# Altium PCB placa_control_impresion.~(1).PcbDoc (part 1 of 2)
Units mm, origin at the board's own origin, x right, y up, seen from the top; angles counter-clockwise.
Board outline 71.3 x 86.83 mm, 2 copper layers (Top Layer, Bottom Layer); 144 components, 32 nets, 580 pads, 404 vias.
Unrouted connection lines stored in the file: 1.
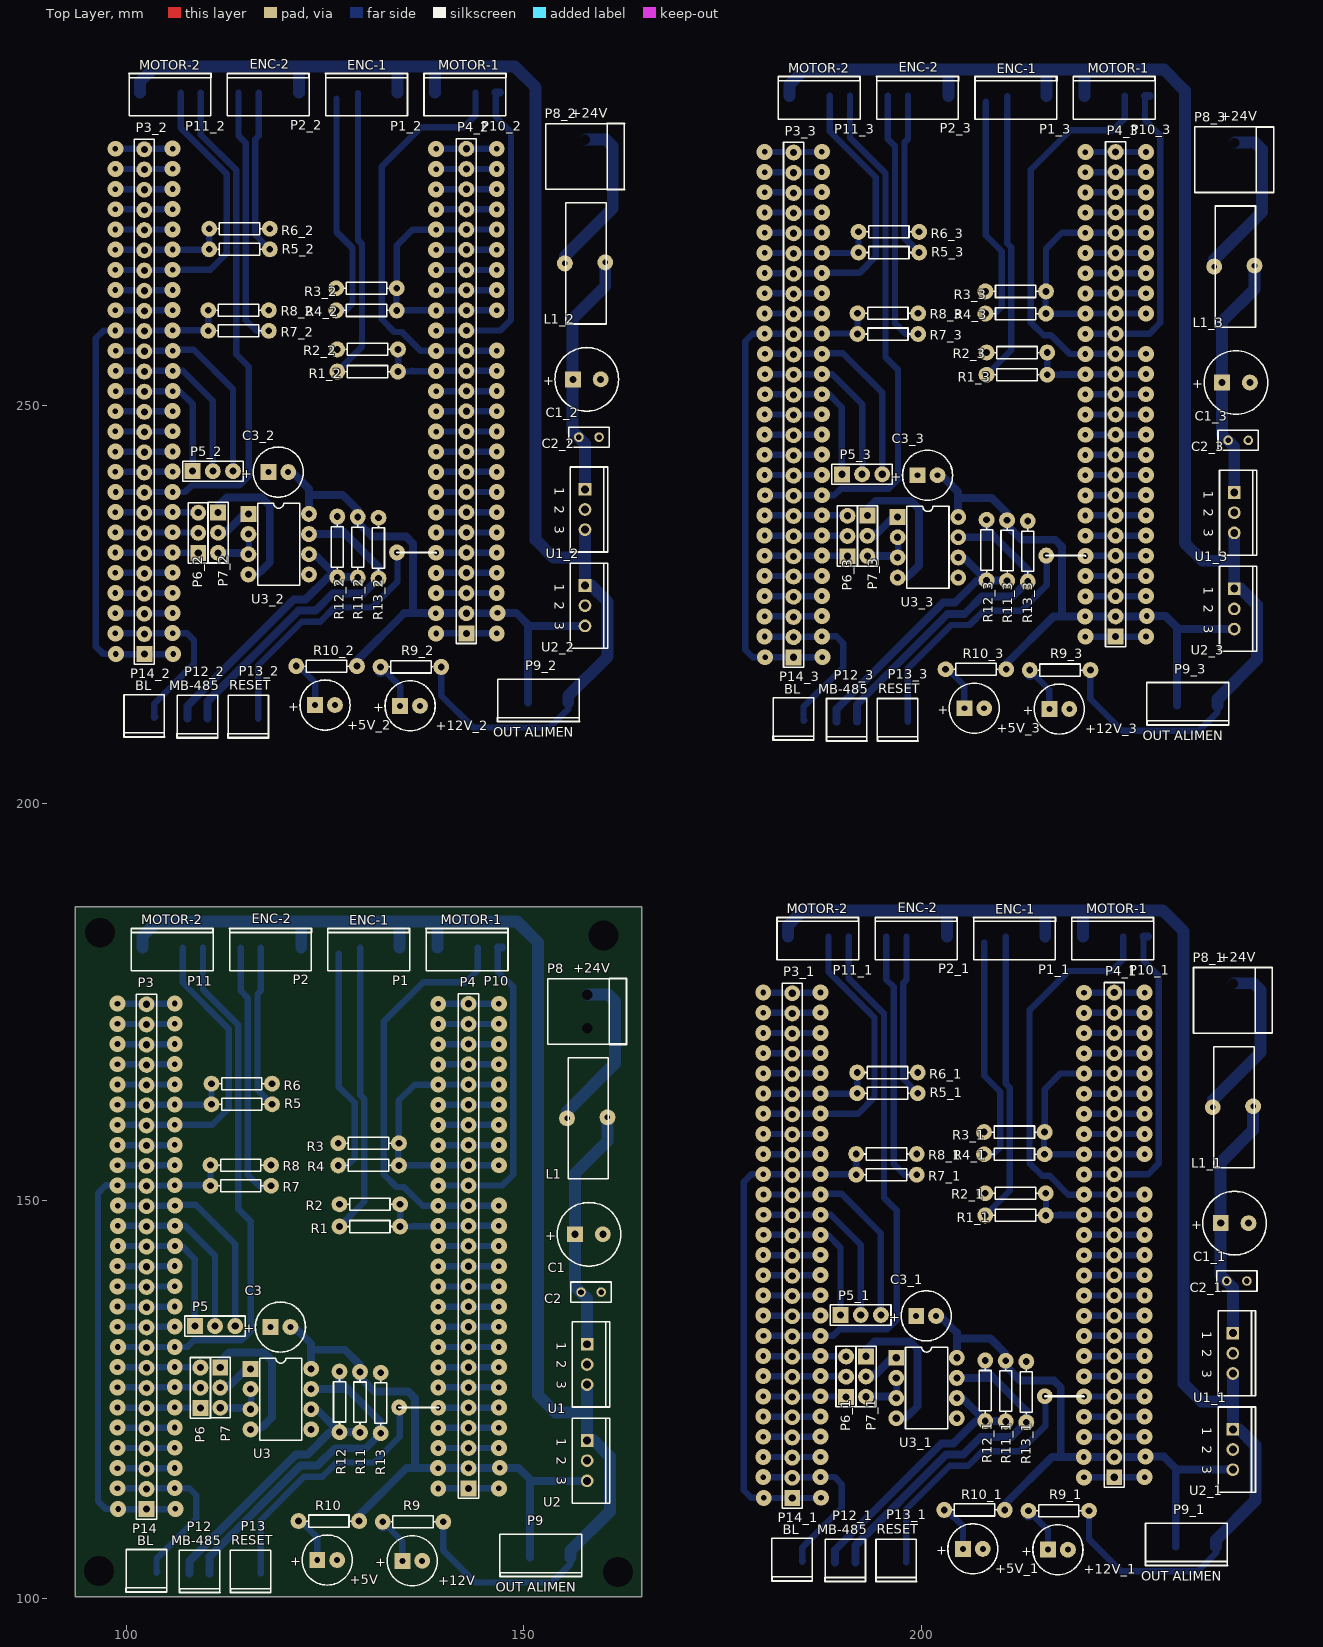
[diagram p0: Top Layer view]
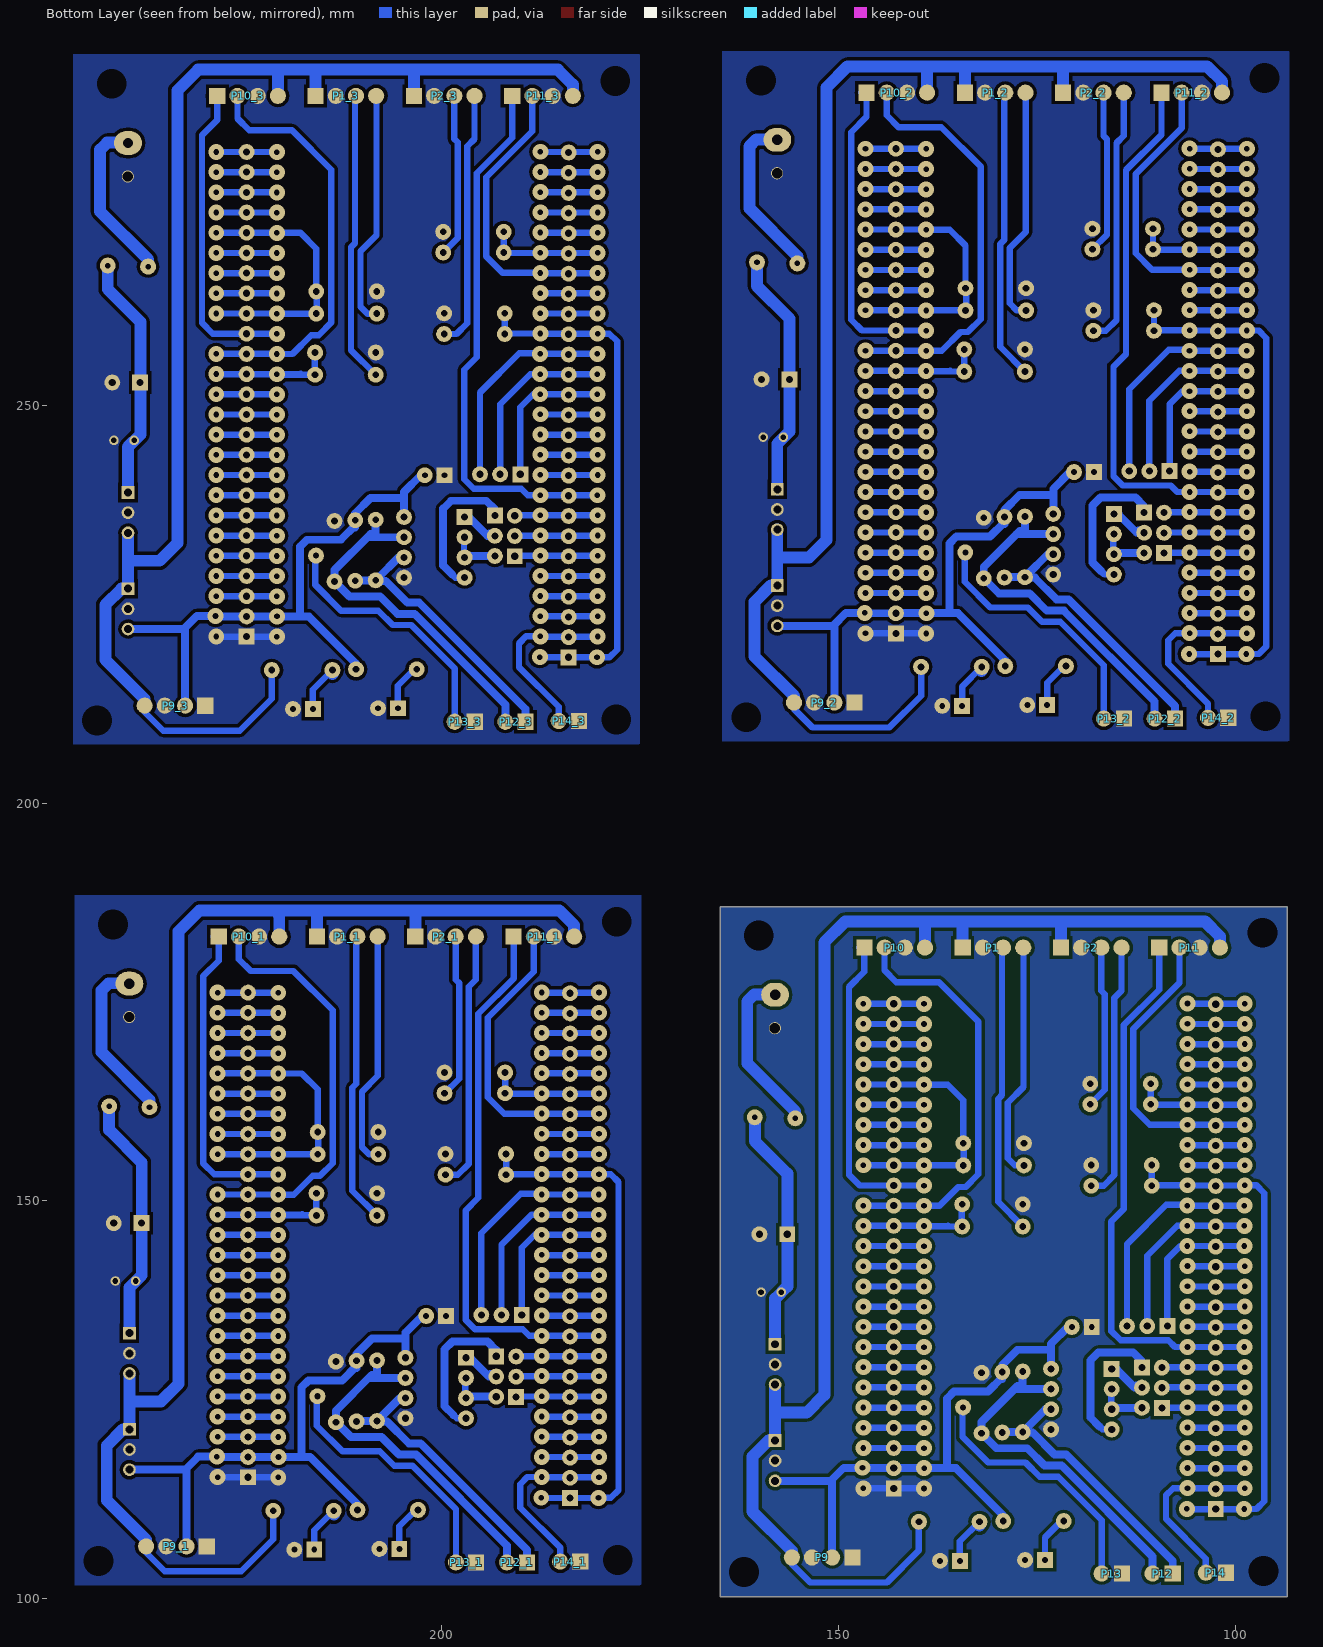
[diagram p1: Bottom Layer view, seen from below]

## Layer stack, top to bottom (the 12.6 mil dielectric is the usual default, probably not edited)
Top Layer: signal copper 0.0356
Dielectric: dielectric 0.32, FR-4, Dk 4.8
Bottom Layer: signal copper 0.0356

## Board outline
93.575,187.025 164.875,187.025 164.875,100.2 93.575,100.2

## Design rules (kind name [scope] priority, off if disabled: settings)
Clearance [All] p1: gap=0.4
ComponentClearance [All] p1: gap=0.254 collisioncheckmode=2 verticalgap=0.254
PlaneConnect [All] p1: planeconnectstyle=Direct reliefexpansion=0.508 reliefentries=4 reliefconductorwidth=0.6 reliefairgap=0.254
PolygonConnect [All] p1: connectstyle=Direct reliefconductorwidth=0.6 reliefentries=4 polygonreliefangle="90 Angle"
RoomDefinition REGULADOR_3 [InComponentClass('REGULADOR')] p1: confinementstyle=ConfineIn formatcopy=TRUE lockcomponents=FALSE outline 201.525,207.325 246.3,207.325 246.3,290.75 201.525,290.75
RoomDefinition INTERFAZ_3 [InComponentClass('INTERFAZ')] p2: confinementstyle=ConfineIn formatcopy=TRUE lockcomponents=FALSE outline 188.5,222.175 221.4,222.175 221.4,247.575 188.5,247.575
RoomDefinition ENCODER_3 [InComponentClass('ENCODER')] p3: confinementstyle=ConfineIn formatcopy=TRUE lockcomponents=FALSE outline 230.725,251.225 230.725,293.45 180.55,293.45 180.55,251.225
RoomDefinition BOARD-ARM_3 [InComponentClass('BOARD-ARM')] p4: confinementstyle=ConfineIn formatcopy=TRUE lockcomponents=FALSE outline 229.663,206.9 177.025,206.9 177.025,287.425 229.663,287.425
RoomDefinition placa_control_esquema_3 [InComponentClass('placa_control_esquema')] p5: confinementstyle=ConfineIn formatcopy=TRUE lockcomponents=FALSE outline 174.975,207.325 246.275,207.325 246.275,294.175 174.975,294.175
RoomDefinition REGULADOR_2 [InComponentClass('REGULADOR')] p6: confinementstyle=ConfineIn formatcopy=TRUE lockcomponents=FALSE outline 119.85,207.725 164.625,207.725 164.625,291.15 119.85,291.15
RoomDefinition INTERFAZ_2 [InComponentClass('INTERFAZ')] p7: confinementstyle=ConfineIn formatcopy=TRUE lockcomponents=FALSE outline 106.825,222.575 139.725,222.575 139.725,247.975 106.825,247.975
RoomDefinition ENCODER_2 [InComponentClass('ENCODER')] p8: confinementstyle=ConfineIn formatcopy=TRUE lockcomponents=FALSE outline 149.05,251.625 149.05,293.85 98.875,293.85 98.875,251.625
RoomDefinition BOARD-ARM_2 [InComponentClass('BOARD-ARM')] p9: confinementstyle=ConfineIn formatcopy=TRUE lockcomponents=FALSE outline 147.988,207.3 95.35,207.3 95.35,287.825 147.988,287.825
RoomDefinition placa_control_esquema_2 [InComponentClass('placa_control_esquema')] p10: confinementstyle=ConfineIn formatcopy=TRUE lockcomponents=FALSE outline 93.3,207.725 164.6,207.725 164.6,294.575 93.3,294.575
RoomDefinition REGULADOR_1 [InComponentClass('REGULADOR')] p11: confinementstyle=ConfineIn formatcopy=TRUE lockcomponents=FALSE outline 201.35,101.575 246.125,101.575 246.125,185 201.35,185
RoomDefinition INTERFAZ_1 [InComponentClass('INTERFAZ')] p12: confinementstyle=ConfineIn formatcopy=TRUE lockcomponents=FALSE outline 188.325,116.425 221.225,116.425 221.225,141.825 188.325,141.825
RoomDefinition ENCODER_1 [InComponentClass('ENCODER')] p13: confinementstyle=ConfineIn formatcopy=TRUE lockcomponents=FALSE outline 230.55,145.475 230.55,187.7 180.375,187.7 180.375,145.475
RoomDefinition BOARD-ARM_1 [InComponentClass('BOARD-ARM')] p14: confinementstyle=ConfineIn formatcopy=TRUE lockcomponents=FALSE outline 229.488,101.15 176.85,101.15 176.85,181.675 229.488,181.675
RoomDefinition placa_control_esquema_1 [InComponentClass('placa_control_esquema')] p15: confinementstyle=ConfineIn formatcopy=TRUE lockcomponents=FALSE outline 174.8,101.575 246.1,101.575 246.1,188.425 174.8,188.425
RoomDefinition REGULADOR [InComponentClass('REGULADOR')] p16: confinementstyle=ConfineIn formatcopy=TRUE lockcomponents=FALSE outline 120.125,100.175 164.9,100.175 164.9,183.6 120.125,183.6
RoomDefinition INTERFAZ [InComponentClass('INTERFAZ')] p17: confinementstyle=ConfineIn formatcopy=TRUE lockcomponents=FALSE outline 107.1,115.025 140,115.025 140,140.425 107.1,140.425
RoomDefinition ENCODER [InComponentClass('ENCODER')] p18: confinementstyle=ConfineIn formatcopy=TRUE lockcomponents=FALSE outline 149.325,144.075 149.325,186.3 99.15,186.3 99.15,144.075
RoomDefinition BOARD-ARM [InComponentClass('BOARD-ARM')] p19: confinementstyle=ConfineIn formatcopy=TRUE lockcomponents=FALSE outline 148.263,99.75 95.625,99.75 95.625,180.275 148.263,180.275
RoomDefinition placa_control_esquema [InComponentClass('placa_control_esquema')] p20: confinementstyle=ConfineIn formatcopy=TRUE lockcomponents=FALSE outline 93.575,100.175 164.875,100.175 164.875,187.025 93.575,187.025
RoutingVias [All] p1: holewidth=0.711 width=2 viastyle="Through Hole" minholewidth=0.711 minwidth=1.27 maxholewidth=0.711 maxwidth=2
SolderMaskExpansion [All] p1: expansion=0.102
TestPointUsage [All] p1: valid=0 allowmultiple=FALSE
Testpoint [All] p1: side=15 testpointundercomponent=TRUE minsize=1.016 maxsize=2.54 preferedsize=1.524 minholesize=0 maxholesize=1.016 preferedholesize=0.813 testpointgrid=0.025 style=1023 order=0-112345678
Width [All] p1: maxlimit=1.5 minlimit=0.8 preferedwidth=0.8
17 further rules are at their usual default settings.

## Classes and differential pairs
component class INTERFAZ: C3 P12 R11 R12 R13 U3
component class ENCODER: P1 P2 R1 R2 R3 R4 R5 R6 R7 R8
component class BOARD-ARM: P3 P4 P5 P6 P7 P13 P14
component class REGULADOR: +5V +12V C1 C2 L1 P8 R9 R10 U1 U2
component class placa_control_esquema: P9 P10 P11

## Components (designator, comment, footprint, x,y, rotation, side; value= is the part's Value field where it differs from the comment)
+5V "LED2" CAPPR2.5-6.3X5 125.275,104.825 r0 top
+5V_1 "LED2" CAPPR2.5-6.3X5 206.5,106.225 r0 top (schematic designator +5V)
+5V_2 "LED2" CAPPR2.5-6.3X5 125,212.375 r0 top (schematic designator +5V)
+5V_3 "LED2" CAPPR2.5-6.3X5 206.675,211.975 r0 top (schematic designator +5V)
+12V "LED2" CAPPR2.5-6.3X5 135.975,104.725 r0 top
+12V_1 "LED2" CAPPR2.5-6.3X5 217.2,106.125 r0 top (schematic designator +12V)
+12V_2 "LED2" CAPPR2.5-6.3X5 135.7,212.275 r0 top (schematic designator +12V)
+12V_3 "LED2" CAPPR2.5-6.3X5 217.375,211.875 r0 top (schematic designator +12V)
C1 "Cap Pol3" CAPPR3.5-8X15 158.2,145.8 r0 top
C1_1 "Cap Pol3" CAPPR3.5-8X15 239.425,147.2 r0 top (schematic designator C1)
C1_2 "Cap Pol3" CAPPR3.5-8X15 157.925,253.35 r0 top (schematic designator C1)
C1_3 "Cap Pol3" CAPPR3.5-8X15 239.6,252.95 r0 top (schematic designator C1)
C2 "Cap" RAD-0.1 158.475,138.525 r180 top
C2_1 "Cap" RAD-0.1 239.7,139.925 r180 top (schematic designator C2)
C2_2 "Cap" RAD-0.1 158.2,246.075 r180 top (schematic designator C2)
C2_3 "Cap" RAD-0.1 239.875,245.675 r180 top (schematic designator C2)
C3 "Cap" CAPPR2.5-6.3X5 119.394,134.133 r0 top
C3_1 "Cap" CAPPR2.5-6.3X5 200.619,135.533 r0 top (schematic designator C3)
C3_2 "Cap" CAPPR2.5-6.3X5 119.119,241.683 r0 top (schematic designator C3)
C3_3 "Cap" CAPPR2.5-6.3X5 200.794,241.283 r0 top (schematic designator C3)
L1 "Inductor Iron" bobina_Choque 155.575,162.925 r270 top
L1_1 "Inductor Iron" bobina_Choque 236.8,164.325 r270 top (schematic designator L1)
L1_2 "Inductor Iron" bobina_Choque 155.3,270.475 r270 top (schematic designator L1)
L1_3 "Inductor Iron" bobina_Choque 236.975,270.075 r270 top (schematic designator L1)
P1 "ENC-1" HDR1X5 126.758,189.475 r180 top
P1_1 "ENC-1" HDR1X5 207.983,190.875 r180 top (schematic designator P1)
P1_2 "ENC-1" HDR1X5 126.483,297.025 r180 top (schematic designator P1)
P1_3 "ENC-1" HDR1X5 208.158,296.625 r180 top (schematic designator P1)
P2 "ENC-2" HDR1X5 114.392,189.475 r180 top
P2_1 "ENC-2" HDR1X5 195.617,190.875 r180 top (schematic designator P2)
P2_2 "ENC-2" HDR1X5 114.117,297.025 r180 top (schematic designator P2)
P2_3 "ENC-2" HDR1X5 195.792,296.625 r180 top (schematic designator P2)
P3 "header26" HDR1x26 107.625,144.25 r90 top
P3_1 "header26" HDR1x26 188.85,145.65 r90 top (schematic designator P3)
P3_2 "header26" HDR1x26 107.35,251.8 r90 top (schematic designator P3)
P3_3 "header26" HDR1x26 189.025,251.4 r90 top (schematic designator P3)
P4 "Header 25" HDR1X25 143.055,113.84 r90 top
P4_1 "Header 25" HDR1X25 224.28,115.24 r90 top (schematic designator P4)
P4_2 "Header 25" HDR1X25 142.78,221.39 r90 top (schematic designator P4)
P4_3 "Header 25" HDR1X25 224.455,220.99 r90 top (schematic designator P4)
P5 "Header 3" HDR1X3 108.625,134.25 r0 top
P5_1 "Header 3" HDR1X3 189.85,135.65 r0 top (schematic designator P5)
P5_2 "Header 3" HDR1X3 108.35,241.8 r0 top (schematic designator P5)
P5_3 "Header 3" HDR1X3 190.025,241.4 r0 top (schematic designator P5)
P6 "Header 3" HDR1X3 109.325,123.95 r90 top
P6_1 "Header 3" HDR1X3 190.55,125.35 r90 top (schematic designator P6)
P6_2 "Header 3" HDR1X3 109.05,231.5 r90 top (schematic designator P6)
P6_3 "Header 3" HDR1X3 190.725,231.1 r90 top (schematic designator P6)
P7 "Header 3" HDR1X3 111.825,129.05 r270 top
P7_1 "Header 3" HDR1X3 193.05,130.45 r270 top (schematic designator P7)
P7_2 "Header 3" HDR1X3 111.55,236.6 r270 top (schematic designator P7)
P7_3 "Header 3" HDR1X3 193.225,236.2 r270 top (schematic designator P7)
P8 "+24V" PWHEADER1X2 157.975,174.025 r90 top
P8_1 "+24V" PWHEADER1X2 239.2,175.425 r90 top (schematic designator P8)
P8_2 "+24V" PWHEADER1X2 157.7,281.575 r90 top (schematic designator P8)
P8_3 "+24V" PWHEADER1X2 239.375,281.175 r90 top (schematic designator P8)
P9 "OUT ALIMEN" HDR1X5 155.875,97.525 r0 top
P9_1 "OUT ALIMEN" HDR1X5 237.1,98.925 r0 top (schematic designator P9)
P9_2 "OUT ALIMEN" HDR1X5 155.6,205.075 r0 top (schematic designator P9)
P9_3 "OUT ALIMEN" HDR1X5 237.275,204.675 r0 top (schematic designator P9)
P10 "MOTOR-1" HDR1X5 139.125,189.475 r180 top
P10_1 "MOTOR-1" HDR1X5 220.35,190.875 r180 top (schematic designator P10)
P10_2 "MOTOR-1" HDR1X5 138.85,297.025 r180 top (schematic designator P10)
P10_3 "MOTOR-1" HDR1X5 220.525,296.625 r180 top (schematic designator P10)
P11 "MOTOR-2" HDR1X5 102.025,189.475 r180 top
P11_1 "MOTOR-2" HDR1X5 183.25,190.875 r180 top (schematic designator P11)
P11_2 "MOTOR-2" HDR1X5 101.75,297.025 r180 top (schematic designator P11)
P11_3 "MOTOR-2" HDR1X5 183.425,296.625 r180 top (schematic designator P11)
P12 "MB-485" wf2s 115.575,103.125 r0 top
P12_1 "MB-485" wf2s 196.8,104.525 r0 top (schematic designator P12)
P12_2 "MB-485" wf2s 115.3,210.675 r0 top (schematic designator P12)
P12_3 "MB-485" wf2s 196.975,210.275 r0 top (schematic designator P12)
P13 "RESET" wf2s 121.975,103.125 r0 top
P13_1 "RESET" wf2s 203.2,104.525 r0 top (schematic designator P13)
P13_2 "RESET" wf2s 121.7,210.675 r0 top (schematic designator P13)
P13_3 "RESET" wf2s 203.375,210.275 r0 top (schematic designator P13)
P14 "BL" wf2s 108.875,103.225 r0 top
P14_1 "BL" wf2s 190.1,104.625 r0 top (schematic designator P14)
P14_2 "BL" wf2s 108.6,210.775 r0 top (schematic designator P14)
P14_3 "BL" wf2s 190.275,210.375 r0 top (schematic designator P14)
R1 "metal film 2%" AXIAL-0.3 130.634,146.777 r180 top
R1_1 "metal film 2%" AXIAL-0.3 211.859,148.177 r180 top (schematic designator R1)
R1_2 "metal film 2%" AXIAL-0.3 130.359,254.327 r180 top (schematic designator R1)
R1_3 "metal film 2%" AXIAL-0.3 212.034,253.927 r180 top (schematic designator R1)
R2 "metal film 2%" AXIAL-0.3 130.634,149.569 r0 top
R2_1 "metal film 2%" AXIAL-0.3 211.859,150.969 r0 top (schematic designator R2)
R2_2 "metal film 2%" AXIAL-0.3 130.359,257.119 r0 top (schematic designator R2)
R2_3 "metal film 2%" AXIAL-0.3 212.034,256.719 r0 top (schematic designator R2)
R3 "metal film 2%" AXIAL-0.3 130.484,154.468 r180 top
R3_1 "metal film 2%" AXIAL-0.3 211.709,155.868 r180 top (schematic designator R3)
R3_2 "metal film 2%" AXIAL-0.3 130.209,262.018 r180 top (schematic designator R3)
R3_3 "metal film 2%" AXIAL-0.3 211.884,261.618 r180 top (schematic designator R3)
R4 "metal film 2%" AXIAL-0.3 130.484,157.26 r0 top
R4_1 "metal film 2%" AXIAL-0.3 211.709,158.66 r0 top (schematic designator R4)
R4_2 "metal film 2%" AXIAL-0.3 130.209,264.81 r0 top (schematic designator R4)
R4_3 "metal film 2%" AXIAL-0.3 211.884,264.41 r0 top (schematic designator R4)
R5 "metal film 2%" AXIAL-0.3 114.525,162.15 r0 top
R5_1 "metal film 2%" AXIAL-0.3 195.75,163.55 r0 top (schematic designator R5)
R5_2 "metal film 2%" AXIAL-0.3 114.25,269.7 r0 top (schematic designator R5)
R5_3 "metal film 2%" AXIAL-0.3 195.925,269.3 r0 top (schematic designator R5)
R6 "metal film 2%" AXIAL-0.3 114.525,164.75 r180 top
R6_1 "metal film 2%" AXIAL-0.3 195.75,166.15 r180 top (schematic designator R6)
R6_2 "metal film 2%" AXIAL-0.3 114.25,272.3 r180 top (schematic designator R6)
R6_3 "metal film 2%" AXIAL-0.3 195.925,271.9 r180 top (schematic designator R6)
R7 "metal film 2%" AXIAL-0.3 114.4,151.9 r0 top
R7_1 "metal film 2%" AXIAL-0.3 195.625,153.3 r0 top (schematic designator R7)
R7_2 "metal film 2%" AXIAL-0.3 114.125,259.45 r0 top (schematic designator R7)
R7_3 "metal film 2%" AXIAL-0.3 195.8,259.05 r0 top (schematic designator R7)
R8 "metal film 2%" AXIAL-0.3 114.4,154.5 r180 top
R8_1 "metal film 2%" AXIAL-0.3 195.625,155.9 r180 top (schematic designator R8)
R8_2 "metal film 2%" AXIAL-0.3 114.125,262.05 r180 top (schematic designator R8)
R8_3 "metal film 2%" AXIAL-0.3 195.8,261.65 r180 top (schematic designator R8)
R9 "Carbon 1/8w 5%" AXIAL-0.3 136.075,109.625 r0 top
R9_1 "Carbon 1/8w 5%" AXIAL-0.3 217.3,111.025 r0 top (schematic designator R9)
R9_2 "Carbon 1/8w 5%" AXIAL-0.3 135.8,217.175 r0 top (schematic designator R9)
R9_3 "Carbon 1/8w 5%" AXIAL-0.3 217.475,216.775 r0 top (schematic designator R9)
R10 "Carbon 1/8w 5%" AXIAL-0.3 125.475,109.725 r0 top
R10_1 "Carbon 1/8w 5%" AXIAL-0.3 206.7,111.125 r0 top (schematic designator R10)
R10_2 "Carbon 1/8w 5%" AXIAL-0.3 125.2,217.275 r0 top (schematic designator R10)
R10_3 "Carbon 1/8w 5%" AXIAL-0.3 206.875,216.875 r0 top (schematic designator R10)
R11 "Carbon 1/8w 5%" AXIAL-0.3 129.4,124.675 r90 top
R11_1 "Carbon 1/8w 5%" AXIAL-0.3 210.625,126.075 r90 top (schematic designator R11)
R11_2 "Carbon 1/8w 5%" AXIAL-0.3 129.125,232.225 r90 top (schematic designator R11)
R11_3 "Carbon 1/8w 5%" AXIAL-0.3 210.8,231.825 r90 top (schematic designator R11)
R12 "Carbon 1/8w 5%" AXIAL-0.3 126.826,124.725 r270 top
R12_1 "Carbon 1/8w 5%" AXIAL-0.3 208.051,126.125 r270 top (schematic designator R12)
R12_2 "Carbon 1/8w 5%" AXIAL-0.3 126.551,232.275 r270 top (schematic designator R12)
R12_3 "Carbon 1/8w 5%" AXIAL-0.3 208.226,231.875 r270 top (schematic designator R12)
R13 "Carbon 1/8w 5%" AXIAL-0.3 132,124.575 r270 top
R13_1 "Carbon 1/8w 5%" AXIAL-0.3 213.225,125.975 r270 top (schematic designator R13)
R13_2 "Carbon 1/8w 5%" AXIAL-0.3 131.725,232.125 r270 top (schematic designator R13)
R13_3 "Carbon 1/8w 5%" AXIAL-0.3 213.4,231.725 r270 top (schematic designator R13)
U1 "LM78L12ACZ" T03B 157.975,129.425 r270 top
U1_1 "LM78L12ACZ" T03B 239.2,130.825 r270 top (schematic designator U1)
U1_2 "LM78L12ACZ" T03B 157.7,236.975 r270 top (schematic designator U1)
U1_3 "LM78L12ACZ" T03B 239.375,236.575 r270 top (schematic designator U1)
U2 "LM78L05ACZ" T03B 157.975,117.325 r270 top
U2_1 "LM78L05ACZ" T03B 239.2,118.725 r270 top (schematic designator U2)
U2_2 "LM78L05ACZ" T03B 157.7,224.875 r270 top (schematic designator U2)
U2_3 "LM78L05ACZ" T03B 239.375,224.475 r270 top (schematic designator U2)
U3 "SN75176BP" 626-05 119.444,125.065 r270 top
U3_1 "SN75176BP" 626-05 200.669,126.465 r270 top (schematic designator U3)
U3_2 "SN75176BP" 626-05 119.169,232.615 r270 top (schematic designator U3)
U3_3 "SN75176BP" 626-05 200.844,232.215 r270 top (schematic designator U3)

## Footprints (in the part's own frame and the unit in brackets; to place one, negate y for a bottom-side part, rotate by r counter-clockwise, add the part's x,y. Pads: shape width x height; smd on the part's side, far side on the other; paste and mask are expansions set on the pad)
626-05 [mm] "DIP; 8 Leads; Row Spacing 7.62 mm; Pitch 2.54 mm"
  rect 2x2 hole 0.9: 1(-3.81,-3.81)
  round 2 hole 0.9: 2(-1.27,-3.81) 3(1.27,-3.81) 4(3.81,-3.81) 5(3.81,3.81) 6(1.27,3.81) 7(-1.27,3.81) 8(-3.81,3.81)
  silkscreen extent -5.15,-2.65 5.15,2.65
AXIAL-0.3 [mm] "Resistor; 2 Leads"
  round 2 hole 0.85: 1(-3.81,0) 2(3.81,0)
  silkscreen extent -2.77,-0.76 2.77,0.76
bobina_Choque [mm]
  round 2 hole 0.7: 1(2.54,-0.127) 2(2.413,4.953)
  silkscreen extent -5.08,0 10.16,5.08
CAPPR2.5-6.3X5 [mm] "Capacitor, Electrolytic, Radial; Body 6.3 x 5 mm (Dia.xH typ); Pin Spacing 2.5 mm (typ)"
  rect 2x2 hole 0.75: 1(-1.25,0)
  round 2 hole 0.75: 2(1.25,0)
  silkscreen extent -3.15,-3.15 3.15,3.15
CAPPR3.5-8X15 [mm] "Capacitor, Electrolytic, Radial; Body 8 x 15 mm (Dia.xH typ); Pin Spacing 3.5 mm (typ)"
  rect 2x2 hole 0.9: 1(-1.75,0)
  round 2 hole 0.9: 2(1.75,0)
  silkscreen extent -4,-4 4,4
HDR1X3 [mm] "Connector; Header; 3 Position"
  rect 2x2 hole 0.9: 1(0,0)
  round 2 hole 0.9: 2(2.54,0) 3(5.08,0)
  silkscreen extent -1.27,-1.27 6.35,1.27
HDR1X5 [mil]
  rect 80x80 smd far side: 1(-300,300)
  round 80 smd far side: 2(-200,300) 3(-100,300) 4(0,300)
  silkscreen extent -350,205 55,415
HDR1X25 [mm] "Connector; Header; 25 Position"
  rect 2x2 hole 0.9: 1(0,0)
  round 2 hole 0.9: 2(2.54,0) 3(5.08,0) 4(7.62,0) 5(10.16,0) 6(12.7,0) 7(15.24,0) 8(17.78,0) 9(20.32,0) 10(22.86,0) 11(25.4,0) 12(27.94,0) 13(30.48,0) 14(33.02,0) 15(35.56,0) 16(38.1,0) 17(40.64,0) 18(43.18,0) 19(45.72,0) 20(48.26,0) 21(50.8,0) 22(53.34,0) 23(55.88,0) 24(58.42,0) 25(60.96,0)
  silkscreen extent -1.27,-1.27 62.23,1.27
HDR1x26 [mm]
  rect 2x2 hole 0.9: 1(-33.02,5.08)
  round 2 hole 0.9: 2(-30.48,5.08) 3(-27.94,5.08) 4(-25.4,5.08) 5(-22.86,5.08) 6(-20.32,5.08) 7(-17.78,5.08) 8(-15.24,5.08) 9(-12.7,5.08) 10(-10.16,5.08) 11(-7.62,5.08) 12(-5.08,5.08) 13(-2.54,5.08) 14(0,5.08) 15(2.54,5.08) 16(5.08,5.08) 17(7.62,5.08) 18(10.16,5.08) 19(12.7,5.08) 20(15.24,5.08) 21(17.78,5.08) 22(20.32,5.08) 23(22.86,5.08) 24(25.4,5.08) 25(27.94,5.08) 26(30.48,5.08)
  silkscreen extent -34.29,3.81 31.75,6.35
PWHEADER1X2 [mm]
  round 0 / inner round 0 / far side oval 3x3.5 hole 1.3: 2(1.905,0)
  silkscreen extent -4.32,-4.95 3.94,4.95
RAD-0.1 [mm] "Indicating Instrument; 2 Leads"
  round 1.2 hole 0.7: 1(-1.27,0) 2(1.27,0)
  silkscreen extent -2.54,-1.27 2.54,1.27
T03B [mm] "TO, Thru-Hole, Vertical, Heatsink Mounted; 3 In-Line Leads; Pitch 2.54 mm"
  rect 1.6x1.6 hole 1: 1(-2.54,0)
  round 1.6 hole 1: 2(0,0) 3(2.54,0)
  silkscreen extent -5.35,-1.85 5.35,2.85
wf2s [mil]
  rect 80x80 smd far side: 1(-300,0)
  round 80 smd far side: 2(-200,0)
  silkscreen extent -350,-95 -150,115

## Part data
+5V +5V_1 +5V_2 +5V_3 +12V +12V_1 +12V_2 +12V_3: "Typical RED, GREEN, YELLOW, AMBER GaAs LED"
C1 C1_1 C1_2 C1_3: "Polarized Capacitor 35V"
C2 C2_1 C2_2 C2_3 C3 C3_1 C3_2 C3_3: "Capacitor"
L1 L1_1 L1_2 L1_3: "Magnetic-Core Inductor"
P1 P1_1 P1_2 P1_3 P2 P2_1 P2_2 P2_3 P9 P9_1 P9_2 P9_3 P10 P10_1 P10_2 P10_3 P11 P11_1 P11_2 P11_3: library part "Header 4", "Header, 4-Pin"
P3 P3_1 P3_2 P3_3: library part Component_1
P4 P4_1 P4_2 P4_3: "Header, 25-Pin"
P5 P5_1 P5_2 P5_3 P6 P6_1 P6_2 P6_3 P7 P7_1 P7_2 P7_3: "Header, 3-Pin"
P8 P8_1 P8_2 P8_3 P12 P12_1 P12_2 P12_3 P13 P13_1 P13_2 P13_3 P14 P14_1 P14_2 P14_3: library part "Header 2", "Header, 2-Pin"
R1 R1_1 R1_2 R1_3 R2 R2_1 R2_2 R2_3 R3 R3_1 R3_2 R3_3 R4 R4_1 R4_2 R4_3 R5 R5_1 R5_2 R5_3 R6 R6_1 R6_2 R6_3 R7 R7_1 R7_2 R7_3 R8 R8_1 R8_2 R8_3 R9 R9_1 R9_2 R9_3 R10 R10_1 R10_2 R10_3 R11 R11_1 R11_2 R11_3 R12 R12_1 R12_2 R12_3 R13 R13_1 R13_2 R13_3: library part "Res Semi", "Semiconductor Resistor"
U1 U1_1 U1_2 U1_3 U2 U2_1 U2_2 U2_3: "3-Terminal Positive Regulator"
U3 U3_1 U3_2 U3_3: "Differential Bus Transceiver"

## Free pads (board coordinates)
  round 1.524 hole 3.75: 0(96.275,210.975) 0(96.4,291.275) 0(96.55,103.425) 0(96.675,183.725) 0(159.75,290.925) 0(160.025,183.375) 0(161.6,210.85) 0(161.875,103.3) 0(177.775,104.825) 0(177.9,185.125) 0(177.95,210.575) 0(178.075,290.875) 0(241.25,184.775) 0(241.425,290.525) 0(243.1,104.7) 0(243.275,210.45)
  round 2 hole 0.762: 0(134.05,231.575) 0(134.325,124.025) 0(215.55,125.425) 0(215.725,231.175)
  round 0 / inner round 0 / far side round 1.524 hole 1.3: 0(157.725,279.275) 0(158,171.725) 0(239.225,173.125) 0(239.4,278.875)

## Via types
v1: diameter 2, hole 0.711, Top Layer to Bottom Layer, 404 vias

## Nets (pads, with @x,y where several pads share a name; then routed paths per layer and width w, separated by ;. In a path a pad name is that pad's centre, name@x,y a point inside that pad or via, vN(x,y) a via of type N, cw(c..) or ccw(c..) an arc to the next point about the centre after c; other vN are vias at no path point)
+5V: C3.2 P4.2 P9.2 R10.2 R11.2 U2.3 U3.8 | length 71.6
  Bottom Layer w1: C3.2@121.142,134.133 123.254,132.021 U3.8@123.254,128.875 U3.8@123.475,128.875 ; 123.254,131.275 127.475,131.275 R11.2@129.4,129.35 ; R10.2@129.285,109.725 129.285,110.435 135.23,116.38 P4.2@143.055,116.38 143.06,116.375 v1@146.325,116.375 ; R11.2@129.4,127.575 129.4,127.825 131.207,126.018 135.457,126.018 136.325,125.15 136.325,116.475 ; v1(146.975,116.425) 149.325,116.425 150.965,114.785 U2.3@157.975,114.785 ; P9.2@150.795,105.145 150.795,114.605
  other v1: 139.225,116.38
+12V: P1.1 P2.1 P9.4 P10.4 P11.4 R9.2 U1.3 U2.1 | length 173.9
  Bottom Layer w0.8: R9.2@139.885,109.625 139.885,106.015 143.9,102 153.55,102 155.875,104.325 P9.4@155.875,105.145
  Bottom Layer w1.5: P11.4@102.025,181.855 102.025,183.275 103.9,185.15 149.15,185.15 151.775,182.525 151.775,125.6 154,123.375 157.975,123.375 ; P2.1@122.012,181.855 122.012,184.637 122.025,184.65 ; P1.1@134.378,181.855 134.378,184.603 134.425,184.65 ; P10.4@139.125,181.855 139.125,184.575 139.2,184.65 ; P9.4@155.875,105.145 155.875,105.975 160.825,110.925 160.825,114.15 ; U1.3@157.975,126.885 U2.1@157.975,119.865 158.785,119.865 160.825,117.825 160.825,114.275
D/~E: P7.3 U3.2 U3.3 | length 6.7
  Bottom Layer w0.8: U3.3@115.634,123.795 115.71,123.87 115.71,126.365 U3.2@115.75,126.325
  Bottom Layer w1: P7.3@111.825,123.97 115.459,123.97 U3.3@115.634,123.795 ; U3.3@115.615,124.27 U3.3@115.71,124.175
D/~E_0: P3.14 P5.1 | length 18.8
  Bottom Layer w0.8: v1(98.94,144.32) 107.005,144.32 108.625,142.7 P5.1@108.625,134.25
  other v1: 106.125,144.32
D/~E_1: P3.6 P6.1 | length 10.4
  Bottom Layer w0.8: v1@98.94,124 109.275,124 P6.1@109.325,123.95
  other v1: 98.9,124.01 106.1,124.025
DRIVER: P7.1 U3.4 | length 18.6
  Bottom Layer w0.8: U3.4@115.634,121.255 116.805,121.255 117.187,121.637
  Bottom Layer w1: P7.1@111.825,129.05 111.825,129.825 112.925,130.925 117.325,130.925 118.325,129.925 118.325,122.775 117.187,121.637
ENC1_FASEZ: P4.17 P4.21 R3.1 R4.2 | length 33.4
  Bottom Layer w0.8: R4.2@134.225,157.375 134.225,154.537 R3.1@134.294,154.468 139.217,154.468 139.235,154.45 v1(139.25,154.465) ; R4.2@134.294,157.26 134.294,162.644 136.275,164.625 v1(139.25,164.625) ; v1@139.555,154.48 v1@146.74,154.48 ; v1@139.555,164.64 v1@146.74,164.64
  other v1: 146.875,154.485 146.875,164.645
ENC2_FASEZ: P3.1 P3.17 R7.1 R8.2 | length 66.1
  Bottom Layer w0.8: v1(98.9,151.95) 97.425,151.95 96.45,150.975 96.45,112.2 97.41,111.24 v1(98.97,111.24) ; v1@98.94,151.94 v1@106.125,151.94 ; v1@99.01,111.23 v1@106.195,111.23 ; v1(106.1,151.965) 110.485,151.965 R7.1@110.65,151.8 ; R7.1@110.59,151.9 R8.2@110.59,154.5
  other v1: 106.17,111.255
GND: +5V.2 +12V.2 C1.2 C2.1 C3.1 P1.2 P2.2 P4.1 P9.1 P9.3 P10.3 P11.3 P13.1 P14.1 pad.0@96.55,103.425 pad.0@96.675,183.725 pad.0@158,171.725 pad.0@160.025,183.375 pad.0@161.875,103.3 R2.1 R4.1 R6.1 R8.1 R13.1 U1.2 U2.2 U3.5 | length 7.2
  Bottom Layer w0.8: v1@139.555,113.84 v1@146.74,113.84
  other v1: 139.25,113.825 146.875,113.845
IN_B_L: P3.2 P14.2 | length 22.2
  Bottom Layer w0.8: v1@98.94,113.84 v1@106.125,113.84 ; P14.2@103.9,103.33 P14.2@103.795,103.225 103.795,104.995 108.8,110 108.8,112.975 107.91,113.865 v1(106.1,113.865)
  other v1: 98.9,113.85
IN_SD_1: P4.15 P10.2 | length 52.2
  Bottom Layer w0.8: v1(139.25,149.385) 137.29,149.385 134.925,151.75 134,151.75 132.4,153.35 132.4,172.575 137.35,177.525 142.725,177.525 144.205,179.005 P10.2@144.205,181.855 ; v1@139.555,149.4 v1@146.74,149.4
  other v1: 146.875,149.405
IN_SD_2: P3.20 P11.2 | length 37.4
  Bottom Layer w0.8: v1@98.94,159.56 v1@106.125,159.56 ; v1(106.1,159.585) 110.835,159.585 112.9,161.65 112.9,171.625 107.105,177.42 P11.2@107.105,181.855
  other v1: 98.9,159.57
Net+5V_1: +5V.1 R10.1 | length 6
  Bottom Layer w0.8: R10.1@121.665,109.725 121.95,109.725 124.025,107.65 +5V.1@124.025,104.825
Net+12V_1: +12V.1 R9.1 | length 6.4
  Bottom Layer w0.8: R9.1@132.265,109.625 134.725,107.165 +12V.1@134.725,104.725
  Bottom Layer w1.5: R9.1@132.265,109.135 R9.1@132.265,109.625
NetC1_1: C1.1 C2.2 L1.2 U1.1 | length 30.9
  Bottom Layer w1.5: U1.1@157.975,131.965 157.975,137.7 156.425,139.25 156.425,153.425 160.528,157.528 L1.2@160.528,160.512
NetL1_1: L1.1 P8.2 | length 21
  Bottom Layer w1.5: L1.1@155.448,160.385 155.448,161.273 161.475,167.3 161.475,175.1 160.6,175.975 P8.2@158.075,175.975
NetP1_3: P1.3 R1.2 | length 36.5
  Bottom Layer w0.8: R1.2@126.824,146.777 129.925,149.878 129.925,162.825 129.425,163.325 P1.3@129.425,181.825
NetP1_4: P1.4 R3.2 | length 29
  Bottom Layer w0.8: R3.2@126.674,154.468 127.843,154.468 128.725,155.35 128.725,162.325 126.725,164.325 P1.4@126.725,181.1
NetP2_3: P2.3 R5.2 | length 20.6
  Bottom Layer w0.8: P2.3@116.932,181.855 116.932,176.434 116.5,176.002 116.5,163.985 R5.2@118.335,162.15
NetP2_4: P2.4 R7.2 | length 32.5
  Bottom Layer w0.8: P2.4@114.392,181.855 114.392,176.433 115.3,175.525 115.3,153.25 116.65,151.9 R7.2@118.21,151.9
NetP3_21: P3.21 R5.1 R6.2 | length 14.6
  Bottom Layer w0.8: v1@98.8,162.1 110.705,162.1 110.715,162.09 R6.2@110.715,164.75
  other v1: 98.9,162.11 106.1,162.125
NetP4_14: P4.14 R1.1 R2.2 | length 17.9
  Bottom Layer w0.8: R1.1@134.444,146.777 139.182,146.777 v1(139.25,146.845) 136.28,146.845 136.225,146.9 ; R1.1@134.475,146.9 R2.2@134.475,149.75 ; v1@139.555,146.86 v1@146.74,146.86
  other v1: 146.875,146.865
NetP12_1: P12.1 R11.1 R12.2 U3.6 | length 33.9
  Bottom Layer w1: P12.1@107.955,103.125 107.955,104.705 121.35,118.1 122.825,118.1 125.575,120.85 126.175,120.85 126.24,120.915 129.35,120.915 R11.1@129.4,120.865 ; U3.6@123.946,123.795 R12.2@126.566,121.175 ; R12.2@126.826,120.915 R12.2@126.826,121.301
NetP12_2: P12.2 R12.1 R13.2 U3.7 | length 45
  Bottom Layer w1: P12.2@110.495,103.125 110.495,105.265 121.93,116.7 124.07,116.7 126.255,118.885 130.11,118.885 132,120.775 132,122.2 127.476,126.724 126.826,126.724 R12.1@126.826,128.535 R12.1@126.866,128.575 ; U3.7@123.254,126.335 127.865,126.335
PWM_1: P4.16 P10.1 | length 39.6
  Bottom Layer w0.8: v1@139.555,151.94 147.315,151.94 148.675,153.3 148.675,176.9 146.745,178.83 P10.1@146.745,181.855
  Bottom Layer w1: P10.1@146.745,181.855 P10.1@147.295,181.855
  other v1: 139.25,151.925
PWM_2: P3.9 P11.1 | length 68.3
  Bottom Layer w0.8: v1(98.94,131.62) 107.67,131.62 108.5,132.45 114.5,132.45 115.675,133.625 115.675,147.4 114.1,148.975 114.1,172.125 109.645,176.58 P11.1@109.645,181.855
  other v1: 106.1,131.62
RECIEVER: P7.2 U3.1 | length 5.1
  Bottom Layer w1: P7.2@111.825,126.51 112.76,126.51 U3.1@115.15,128.9 ; P7.2@112.425,126.8 P7.2@112.525,126.8 ; U3.1@115.05,128.9 U3.1@115.775,128.9
RESET: P4.5 P13.2 pad.0@134.325,124.025 | length 39.4
  Bottom Layer w0.8: P13.2@116.895,103.125 116.895,109.827 122.364,115.295 124.67,115.295 126.475,117.1 131.175,117.1 134.4,120.325 pad.0@134.4,124 ; v1@139.555,124 v1@146.74,124
  other v1: 139.25,123.985 146.875,124.005
RX_0: P3.15 P5.2 | length 22.6
  Bottom Layer w0.8: v1(98.94,146.86) 107.39,146.86 111.165,143.085 P5.2@111.165,134.25
  other v1: 106.125,146.86
RX_1: P3.7 P6.2 | length 10.4
  Bottom Layer w0.8: v1@98.94,126.54 109.275,126.54 P6.2@109.325,126.49
  other v1: 98.9,126.55 106.1,126.565
TX_0: P3.16 P5.3 | length 27.1
  Bottom Layer w0.8: v1(98.94,149.4) v1(106.125,149.4) ; v1@106.15,149.5 108.75,149.5 113.705,144.545 P5.3@113.705,134.25
TX_1: P3.8 P6.3 | length 10.4
  Bottom Layer w0.8: v1@98.94,129.08 109.275,129.08 P6.3@109.325,129.03
  other v1: 98.9,129.09 106.1,129.105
